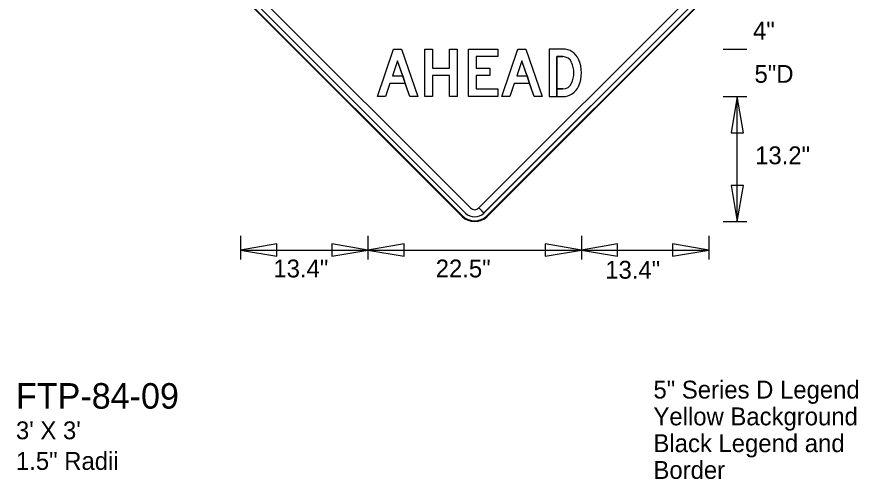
# Model space of a CAD drawing. Extents: x 0 to 770, y 0 to 495.
# Drawn here: x 584 to 749, y 1.2 to 91.9 of the extents above; entities that cross this region are included whole.
import ezdxf

# ---------------------------------------------------------------- set-up
doc = ezdxf.new("R2010")
doc.units = 0
for name, color, linetype in [('Dimension', 7, 'Continuous'), ('GSBWFill', 7, 'Continuous'), ('GSColorFill', 7, 'Continuous'), ('GSDims', 7, 'Continuous'), ('GSOutline', 7, 'Continuous'), ('TextStructures', 7, 'Continuous')]:
    doc.layers.add(name, color=color, linetype=linetype)

msp = doc.modelspace()

# ---------------------------------------------------------------- linework, layer by layer
at = {"layer": 'Dimension'}
for points in [[(725.26, 76.24), (724.05, 69.14), (726.46, 69.14)], [(725.26, 51.73), (726.46, 58.83), (724.05, 58.83)], [(627.87, 46.15), (634.97, 44.95), (634.97, 47.35)], [(652.85, 46.15), (645.74, 47.35), (645.74, 44.95)], [(652.85, 46.15), (659.95, 44.95), (659.95, 47.35)], [(694.7, 46.15), (687.6, 47.35), (687.6, 44.95)], [(694.7, 46.15), (701.8, 44.95), (701.8, 47.35)], [(719.68, 46.15), (712.57, 47.35), (712.57, 44.95)]]:
    msp.add_lwpolyline(points, close=True, dxfattribs=at)
at = {"layer": 'GSBWFill'}
for p, q in [((629.55, 95.83), (671.96, 53.41)), ((672.95, 54.4), (630.54, 96.81)), ((717.01, 96.81), (674.6, 54.41)), ((675.59, 53.42), (717.99, 95.83)), ((628.89, 95.17), (671.3, 52.75)), ((676.24, 52.75), (718.65, 95.17)), ((691.07, 77.73), (689.86, 77.73)), ((675.58, 53.41), (674.59, 54.4)), ((674.6, 54.41), (675.59, 53.42))]:
    msp.add_line(p, q, dxfattribs=at)
for points in [[(654.71, 76.24), (657.87, 85.54), (659.45, 85.54), (662.61, 76.24), (661.04, 76.24), (658.66, 83.25), (657.65, 80.29), (659.66, 80.29), (660.17, 78.8), (657.15, 78.8), (656.28, 76.24)], [(664.01, 85.54), (665.5, 85.54), (665.5, 81.82), (668.84, 81.82), (668.84, 85.54), (670.33, 85.54), (670.33, 76.24), (668.84, 76.24), (668.84, 80.34), (665.5, 80.34), (665.5, 76.24), (664.01, 76.24)], [(678.33, 84.06), (674.05, 84.06), (674.05, 81.82), (676.76, 81.82), (676.76, 80.34), (674.05, 80.34), (674.05, 77.73), (678.33, 77.73), (678.33, 76.24), (672.56, 76.24), (672.56, 85.54), (678.33, 85.54)], [(679.07, 76.24), (682.24, 85.54), (683.82, 85.54), (686.98, 76.24), (685.41, 76.24), (683.03, 83.25), (682.02, 80.29), (684.03, 80.29), (684.54, 78.8), (681.51, 78.8), (680.65, 76.24)]]:
    msp.add_lwpolyline(points, close=True, dxfattribs=at)
for points in [[(691.07, 85.54), (688.37, 85.54), (688.37, 76.24), (689.86, 76.24), (689.86, 84.06), (691.07, 84.06)], [(689.86, 77.73), (689.86, 76.24), (691.07, 76.24)]]:
    msp.add_lwpolyline(points, dxfattribs=at)
for radius in [2.56, 1.16, 3.49]:
    msp.add_arc((673.77, 55.22), radius, 225, 315, dxfattribs=at)
for centre, major_axis, start_param, end_param in [((691.07, 82.2), (0, 3.35), 5.13024, 6.283185), ((691.07, 82.2), (0, 1.86), 5.13024, 6.283185), ((688.14, 80.89), (0, 5.07), 4.294538, 5.13024), ((688.14, 80.89), (0, 6.56), 4.294538, 5.13024), ((691.07, 79.59), (0, 1.86), 3.141593, 4.294538), ((691.07, 79.59), (0, 3.35), 3.141593, 4.294538)]:
    msp.add_ellipse(centre, major_axis=major_axis, ratio=0.999993, start_param=start_param, end_param=end_param, dxfattribs=at)
at = {"layer": 'GSColorFill'}
for p, q in [((629.55, 95.83), (671.96, 53.41)), ((672.95, 54.4), (630.54, 96.81)), ((717.01, 96.81), (674.6, 54.41)), ((675.59, 53.42), (717.99, 95.83)), ((628.89, 95.17), (671.3, 52.75)), ((628.89, 95.17), (671.3, 52.75)), ((671.4, 52.85), (628.99, 95.26)), ((718.56, 95.26), (676.14, 52.85)), ((676.24, 52.75), (718.65, 95.17)), ((676.24, 52.75), (718.65, 95.17)), ((691.07, 77.73), (689.86, 77.73)), ((675.58, 53.41), (674.59, 54.4)), ((674.6, 54.41), (675.59, 53.42)), ((676.24, 52.75), (676.14, 52.85)), ((676.14, 52.85), (676.24, 52.75))]:
    msp.add_line(p, q, dxfattribs=at)
for points in [[(654.71, 76.24), (657.87, 85.54), (659.45, 85.54), (662.61, 76.24), (661.04, 76.24), (658.66, 83.25), (657.65, 80.29), (659.66, 80.29), (660.17, 78.8), (657.15, 78.8), (656.28, 76.24)], [(664.01, 85.54), (665.5, 85.54), (665.5, 81.82), (668.84, 81.82), (668.84, 85.54), (670.33, 85.54), (670.33, 76.24), (668.84, 76.24), (668.84, 80.34), (665.5, 80.34), (665.5, 76.24), (664.01, 76.24)], [(678.33, 84.06), (674.05, 84.06), (674.05, 81.82), (676.76, 81.82), (676.76, 80.34), (674.05, 80.34), (674.05, 77.73), (678.33, 77.73), (678.33, 76.24), (672.56, 76.24), (672.56, 85.54), (678.33, 85.54)], [(679.07, 76.24), (682.24, 85.54), (683.82, 85.54), (686.98, 76.24), (685.41, 76.24), (683.03, 83.25), (682.02, 80.29), (684.03, 80.29), (684.54, 78.8), (681.51, 78.8), (680.65, 76.24)]]:
    msp.add_lwpolyline(points, close=True, dxfattribs=at)
for points in [[(691.07, 85.54), (688.37, 85.54), (688.37, 76.24), (689.86, 76.24), (689.86, 84.06), (691.07, 84.06)], [(689.86, 77.73), (689.86, 76.24), (691.07, 76.24)]]:
    msp.add_lwpolyline(points, dxfattribs=at)
for radius in [3.35, 2.56, 1.16, 3.49, 3.49]:
    msp.add_arc((673.77, 55.22), radius, 225, 315, dxfattribs=at)
for centre, major_axis, start_param, end_param in [((691.07, 82.2), (0, 3.35), 5.13024, 6.283185), ((691.07, 82.2), (0, 1.86), 5.13024, 6.283185), ((688.14, 80.89), (0, 5.07), 4.294538, 5.13024), ((688.14, 80.89), (0, 6.56), 4.294538, 5.13024), ((691.07, 79.59), (0, 1.86), 3.141593, 4.294538), ((691.07, 79.59), (0, 3.35), 3.141593, 4.294538)]:
    msp.add_ellipse(centre, major_axis=major_axis, ratio=0.999993, start_param=start_param, end_param=end_param, dxfattribs=at)
at = {"layer": 'GSDims'}
for p, q in [((722.47, 85.54), (727.12, 85.54)), ((722.47, 85.54), (727.12, 85.54)), ((722.47, 76.24), (727.12, 76.24)), ((722.47, 76.24), (727.12, 76.24)), ((725.26, 51.73), (725.26, 76.24)), ((722.47, 51.73), (727.12, 51.73)), ((627.87, 48.94), (627.87, 44.29)), ((652.85, 48.94), (652.85, 44.29)), ((652.85, 48.94), (652.85, 44.29)), ((694.7, 48.94), (694.7, 44.29)), ((694.7, 48.94), (694.7, 44.29)), ((719.68, 48.94), (719.68, 44.29)), ((627.87, 46.15), (652.85, 46.15)), ((652.85, 46.15), (694.7, 46.15)), ((694.7, 46.15), (719.68, 46.15))]:
    msp.add_line(p, q, dxfattribs=at)
at = {"layer": 'GSOutline'}
for p, q in [((629.55, 95.83), (671.96, 53.41)), ((630.54, 96.81), (672.95, 54.4)), ((674.59, 54.4), (717.01, 96.81)), ((675.58, 53.41), (717.99, 95.83)), ((628.89, 95.17), (671.3, 52.75)), ((676.24, 52.75), (718.65, 95.17)), ((691.07, 85.54), (688.37, 85.54)), ((691.07, 84.06), (689.86, 84.06))]:
    msp.add_line(p, q, dxfattribs=at)
for points in [[(657.15, 78.8), (656.28, 76.24), (654.71, 76.24), (657.87, 85.54), (659.45, 85.54), (662.61, 76.24), (661.04, 76.24), (660.17, 78.8)], [(664.01, 85.54), (665.5, 85.54), (665.5, 81.82), (668.84, 81.82), (668.84, 85.54), (670.33, 85.54), (670.33, 76.24), (668.84, 76.24), (668.84, 80.34), (665.5, 80.34), (665.5, 76.24), (664.01, 76.24)], [(678.33, 84.06), (674.05, 84.06), (674.05, 81.82), (676.76, 81.82), (676.76, 80.34), (674.05, 80.34), (674.05, 77.73), (678.33, 77.73), (678.33, 76.24), (672.56, 76.24), (672.56, 85.54), (678.33, 85.54)], [(681.51, 78.8), (680.65, 76.24), (679.07, 76.24), (682.24, 85.54), (683.82, 85.54), (686.98, 76.24), (685.41, 76.24), (684.54, 78.8)], [(657.65, 80.29), (659.66, 80.29), (658.66, 83.25)], [(682.02, 80.29), (684.03, 80.29), (683.03, 83.25)]]:
    msp.add_lwpolyline(points, close=True, dxfattribs=at)
for points in [[(688.37, 85.54), (688.37, 76.24), (691.07, 76.24)], [(689.86, 84.06), (689.86, 77.73), (691.07, 77.73)]]:
    msp.add_lwpolyline(points, dxfattribs=at)
for radius in [2.56, 1.16, 3.49]:
    msp.add_arc((673.77, 55.22), radius, 225, 315, dxfattribs=at)
for centre, major_axis, start_param, end_param in [((691.07, 82.2), (0, 3.35), 5.13024, 6.283185), ((691.07, 82.2), (0, 1.86), 5.13024, 6.283185), ((688.14, 80.89), (0, 5.07), 4.294538, 5.13024), ((688.14, 80.89), (0, 6.56), 4.294538, 5.13024), ((691.07, 79.59), (0, 1.86), 3.141593, 4.294538), ((691.07, 79.59), (0, 3.35), 3.141593, 4.294538)]:
    msp.add_ellipse(centre, major_axis=major_axis, ratio=0.999993, start_param=start_param, end_param=end_param, dxfattribs=at)

# ---------------------------------------------------------------- texts
at = {"layer": 'GSDims'}
for s, p in [('4"', (728.34, 87.41)), ('5"D', (728.63, 78.94)), ('13.2"', (728.75, 62.97)), ('13.4"', (634.31, 40.79)), ('22.5"', (666.13, 40.79)), ('13.4"', (699.37, 40.54))]:
    msp.add_text(s, height=3.5, dxfattribs=at).set_placement(p)
at = {"layer": 'TextStructures'}
for s, height, p in [('FTP-84-09', 5, (583.84, 15.07)), ('5" Series D Legend', 3.5, (708.82, 17.05)), ('Yellow Background', 3.5, (708.82, 11.8)), ("3' X 3' ", 3.5, (583.84, 9.07)), ('Black Legend and', 3.5, (708.82, 6.55)), ('1.5" Radii', 3.5, (583.84, 3.07)), ('Border', 3.5, (708.82, 1.3))]:
    msp.add_text(s, height=height, dxfattribs=at).set_placement(p)

doc.saveas('drawing.dxf')
